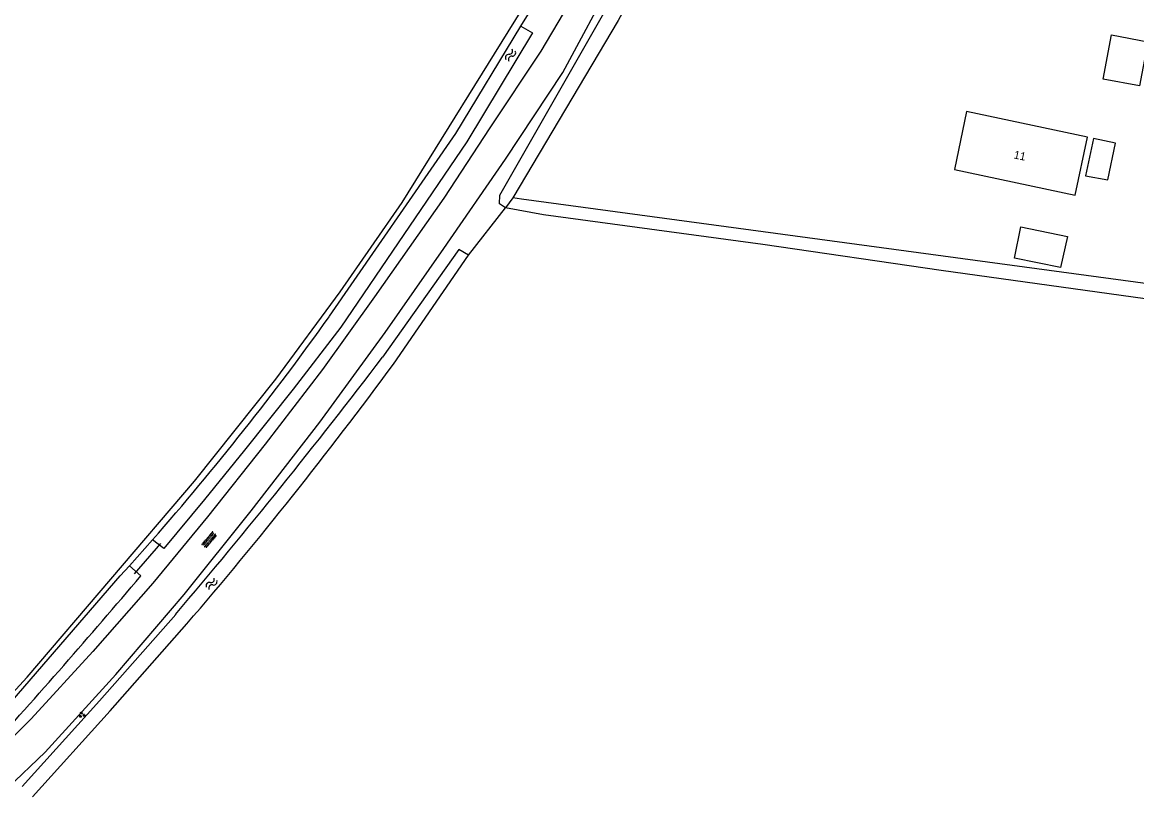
# Model space of a CAD drawing. Extents: x 124000 to 129000, y 395500 to 397503.
# Drawn here: x 125677 to 125816.2, y 397125.3 to 397221.4 of the extents above; entities that cross this region are included whole.
import ezdxf

# ---------------------------------------------------------------- set-up
doc = ezdxf.new("R2010")
doc.units = 0
for name, color, linetype in [('gg-afsc-draadraster', 7, 'Continuous'), ('gg-anno-huisnummerreeks BGT', 7, 'Continuous'), ('gg-bbg-bijgebouw', 7, 'Continuous'), ('gg-bbg-hoofdgebouw', 7, 'Continuous'), ('gg-bbg-luifel en loopbrug', 7, 'Continuous'), ('gg-bbg-open loods', 7, 'Continuous'), ('gg-knt-onverhard', 7, 'Continuous'), ('gg-kntw-bovenkant insteek waterloop', 7, 'Continuous'), ('gg-kwrk-duiker nz buis', 7, 'Continuous'), ('gg-kwrk-stuw', 7, 'Continuous'), ('gt-grn-groengrens', 7, 'Continuous'), ('gt-grn-vlakafsluiter', 7, 'Continuous'), ('gt-symb-groenvak', 7, 'Continuous'), ('gt-symb-overige verharding', 7, 'Continuous'), ('gt-symb-watersymbool', 7, 'Continuous')]:
    doc.layers.add(name, color=color, linetype=linetype)

# ---------------------------------------------------------------- blocks, each defined once
blk = doc.blocks.new('gt0-WA')
at = {"layer": 'gt-symb-watersymbool'}
for centre, start, end in [((-0.32, 0.02), 28.0725, 151.9275), ((0.43, 0.42), 208.0725, 331.9275), ((-0.32, -0.43), 28.0725, 151.9275), ((0.43, -0.03), 208.0725, 331.9275)]:
    blk.add_arc(centre, 0.425, start, end, dxfattribs=at)
blk = doc.blocks.new('gt0-GRVAK')
at = {"layer": 'gt-symb-groenvak'}
for p, q in [((-0.11, 0.19), (-0.23, 0.24)), ((-0.18, 0.15), (0.09, 0.15)), ((-0.09, 0.21), (-0.16, 0.32)), ((-0.05, 0.21), (-0.05, 0.39)), ((0, 0.21), (0.06, 0.32)), ((0.01, 0.19), (0.13, 0.24)), ((0.26, -0.05), (0.2, 0.06)), ((0.3, -0.05), (0.3, 0.13)), ((0.35, -0.05), (0.41, 0.06)), ((-0.25, -0.23), (-0.36, -0.18)), ((-0.32, -0.26), (-0.05, -0.26)), ((-0.23, -0.21), (-0.29, -0.09)), ((-0.18, -0.2), (-0.18, -0.02)), ((-0.14, -0.21), (-0.07, -0.09)), ((-0.12, -0.23), (0, -0.18)), ((0.24, -0.07), (0.12, -0.02)), ((0.17, -0.11), (0.44, -0.11)), ((0.37, -0.07), (0.49, -0.02))]:
    blk.add_line(p, q, dxfattribs=at)
blk = doc.blocks.new('gt0-OVH')
at = {"layer": 'gt-symb-overige verharding'}
for points in [[(-0.97, 0.3), (-0.97, 0.31), (-0.96, 0.32), (-0.97, 0.33), (-0.97, 0.34), (-0.98, 0.35), (-0.99, 0.35), (-1, 0.36), (-1.01, 0.35), (-1.02, 0.35), (-1.03, 0.34), (-1.03, 0.33), (-1.04, 0.32), (-1.03, 0.31), (-1.03, 0.3), (-1.02, 0.29), (-1.01, 0.29), (-1, 0.28), (-0.99, 0.29), (-0.98, 0.29)], [(-0.87, 0.11), (-0.87, 0.12), (-0.86, 0.13), (-0.87, 0.14), (-0.87, 0.15), (-0.88, 0.16), (-0.89, 0.16), (-0.9, 0.16), (-0.91, 0.16), (-0.92, 0.16), (-0.93, 0.15), (-0.93, 0.14), (-0.94, 0.13), (-0.93, 0.12), (-0.93, 0.11), (-0.92, 0.1), (-0.91, 0.09), (-0.9, 0.09), (-0.89, 0.09), (-0.88, 0.1)], [(-0.77, 0.3), (-0.77, 0.31), (-0.76, 0.32), (-0.77, 0.33), (-0.77, 0.34), (-0.78, 0.35), (-0.79, 0.35), (-0.8, 0.36), (-0.81, 0.35), (-0.82, 0.35), (-0.83, 0.34), (-0.83, 0.33), (-0.84, 0.32), (-0.83, 0.31), (-0.83, 0.3), (-0.82, 0.29), (-0.81, 0.29), (-0.8, 0.28), (-0.79, 0.29), (-0.78, 0.29)], [(-0.67, 0.11), (-0.67, 0.12), (-0.66, 0.13), (-0.67, 0.14), (-0.67, 0.15), (-0.68, 0.16), (-0.69, 0.16), (-0.7, 0.16), (-0.71, 0.16), (-0.72, 0.16), (-0.73, 0.15), (-0.73, 0.14), (-0.74, 0.13), (-0.73, 0.12), (-0.73, 0.11), (-0.72, 0.1), (-0.71, 0.09), (-0.7, 0.09), (-0.69, 0.09), (-0.68, 0.1)], [(-0.57, 0.3), (-0.57, 0.31), (-0.56, 0.32), (-0.57, 0.33), (-0.57, 0.34), (-0.58, 0.35), (-0.59, 0.35), (-0.6, 0.36), (-0.61, 0.35), (-0.62, 0.35), (-0.63, 0.34), (-0.63, 0.33), (-0.64, 0.32), (-0.63, 0.31), (-0.63, 0.3), (-0.62, 0.29), (-0.61, 0.29), (-0.6, 0.28), (-0.59, 0.29), (-0.58, 0.29)], [(-0.47, 0.11), (-0.47, 0.12), (-0.46, 0.13), (-0.47, 0.14), (-0.47, 0.15), (-0.48, 0.16), (-0.49, 0.16), (-0.5, 0.16), (-0.51, 0.16), (-0.52, 0.16), (-0.53, 0.15), (-0.53, 0.14), (-0.54, 0.13), (-0.53, 0.12), (-0.53, 0.11), (-0.52, 0.1), (-0.51, 0.09), (-0.5, 0.09), (-0.49, 0.09), (-0.48, 0.1)], [(-0.37, 0.3), (-0.37, 0.31), (-0.36, 0.32), (-0.37, 0.33), (-0.37, 0.34), (-0.38, 0.35), (-0.39, 0.35), (-0.4, 0.36), (-0.41, 0.35), (-0.42, 0.35), (-0.43, 0.34), (-0.43, 0.33), (-0.44, 0.32), (-0.43, 0.31), (-0.43, 0.3), (-0.42, 0.29), (-0.41, 0.29), (-0.4, 0.28), (-0.39, 0.29), (-0.38, 0.29)], [(-0.27, 0.11), (-0.27, 0.12), (-0.26, 0.13), (-0.27, 0.14), (-0.27, 0.15), (-0.28, 0.16), (-0.29, 0.16), (-0.3, 0.16), (-0.31, 0.16), (-0.32, 0.16), (-0.33, 0.15), (-0.33, 0.14), (-0.34, 0.13), (-0.33, 0.12), (-0.33, 0.11), (-0.32, 0.1), (-0.31, 0.09), (-0.3, 0.09), (-0.29, 0.09), (-0.28, 0.1)], [(-0.17, 0.3), (-0.17, 0.31), (-0.16, 0.32), (-0.17, 0.33), (-0.17, 0.34), (-0.18, 0.35), (-0.19, 0.35), (-0.2, 0.36), (-0.21, 0.35), (-0.22, 0.35), (-0.23, 0.34), (-0.23, 0.33), (-0.24, 0.32), (-0.23, 0.31), (-0.23, 0.3), (-0.22, 0.29), (-0.21, 0.29), (-0.2, 0.28), (-0.19, 0.29), (-0.18, 0.29)], [(-0.07, 0.11), (-0.07, 0.12), (-0.06, 0.13), (-0.07, 0.14), (-0.07, 0.15), (-0.08, 0.16), (-0.09, 0.16), (-0.1, 0.16), (-0.11, 0.16), (-0.12, 0.16), (-0.13, 0.15), (-0.13, 0.14), (-0.14, 0.13), (-0.13, 0.12), (-0.13, 0.11), (-0.12, 0.1), (-0.11, 0.09), (-0.1, 0.09), (-0.09, 0.09), (-0.08, 0.1)], [(0.03, 0.3), (0.03, 0.31), (0.04, 0.32), (0.03, 0.33), (0.03, 0.34), (0.02, 0.35), (0.01, 0.35), (0, 0.36), (-0.01, 0.35), (-0.02, 0.35), (-0.03, 0.34), (-0.03, 0.33), (-0.04, 0.32), (-0.03, 0.31), (-0.03, 0.3), (-0.02, 0.29), (-0.01, 0.29), (0, 0.28), (0.01, 0.29), (0.02, 0.29)], [(0.13, 0.11), (0.13, 0.12), (0.14, 0.13), (0.13, 0.14), (0.13, 0.15), (0.12, 0.16), (0.11, 0.16), (0.1, 0.16), (0.09, 0.16), (0.08, 0.16), (0.07, 0.15), (0.07, 0.14), (0.06, 0.13), (0.07, 0.12), (0.07, 0.11), (0.08, 0.1), (0.09, 0.09), (0.1, 0.09), (0.11, 0.09), (0.12, 0.1)], [(0.23, 0.3), (0.23, 0.31), (0.24, 0.32), (0.23, 0.33), (0.23, 0.34), (0.22, 0.35), (0.21, 0.35), (0.2, 0.36), (0.19, 0.35), (0.18, 0.35), (0.17, 0.34), (0.17, 0.33), (0.16, 0.32), (0.17, 0.31), (0.17, 0.3), (0.18, 0.29), (0.19, 0.29), (0.2, 0.28), (0.21, 0.29), (0.22, 0.29)], [(0.33, 0.11), (0.33, 0.12), (0.34, 0.13), (0.33, 0.14), (0.33, 0.15), (0.32, 0.16), (0.31, 0.16), (0.3, 0.16), (0.29, 0.16), (0.28, 0.16), (0.27, 0.15), (0.27, 0.14), (0.26, 0.13), (0.27, 0.12), (0.27, 0.11), (0.28, 0.1), (0.29, 0.09), (0.3, 0.09), (0.31, 0.09), (0.32, 0.1)], [(0.43, 0.3), (0.43, 0.31), (0.44, 0.32), (0.43, 0.33), (0.43, 0.34), (0.42, 0.35), (0.41, 0.35), (0.4, 0.36), (0.39, 0.35), (0.38, 0.35), (0.37, 0.34), (0.37, 0.33), (0.36, 0.32), (0.37, 0.31), (0.37, 0.3), (0.38, 0.29), (0.39, 0.29), (0.4, 0.28), (0.41, 0.29), (0.42, 0.29)], [(0.53, 0.11), (0.53, 0.12), (0.54, 0.13), (0.53, 0.14), (0.53, 0.15), (0.52, 0.16), (0.51, 0.16), (0.5, 0.16), (0.49, 0.16), (0.48, 0.16), (0.47, 0.15), (0.47, 0.14), (0.46, 0.13), (0.47, 0.12), (0.47, 0.11), (0.48, 0.1), (0.49, 0.09), (0.5, 0.09), (0.51, 0.09), (0.52, 0.1)], [(0.63, 0.3), (0.63, 0.31), (0.64, 0.32), (0.63, 0.33), (0.63, 0.34), (0.62, 0.35), (0.61, 0.35), (0.6, 0.36), (0.59, 0.35), (0.58, 0.35), (0.57, 0.34), (0.57, 0.33), (0.56, 0.32), (0.57, 0.31), (0.57, 0.3), (0.58, 0.29), (0.59, 0.29), (0.6, 0.28), (0.61, 0.29), (0.62, 0.29)], [(0.73, 0.11), (0.73, 0.12), (0.74, 0.13), (0.73, 0.14), (0.73, 0.15), (0.72, 0.16), (0.71, 0.16), (0.7, 0.16), (0.69, 0.16), (0.68, 0.16), (0.67, 0.15), (0.67, 0.14), (0.66, 0.13), (0.67, 0.12), (0.67, 0.11), (0.68, 0.1), (0.69, 0.09), (0.7, 0.09), (0.71, 0.09), (0.72, 0.1)], [(0.83, 0.3), (0.83, 0.31), (0.84, 0.32), (0.83, 0.33), (0.83, 0.34), (0.82, 0.35), (0.81, 0.35), (0.8, 0.36), (0.79, 0.35), (0.78, 0.35), (0.77, 0.34), (0.77, 0.33), (0.76, 0.32), (0.77, 0.31), (0.77, 0.3), (0.78, 0.29), (0.79, 0.29), (0.8, 0.28), (0.81, 0.29), (0.82, 0.29)], [(0.93, 0.11), (0.93, 0.12), (0.94, 0.13), (0.93, 0.14), (0.93, 0.15), (0.92, 0.16), (0.91, 0.16), (0.9, 0.16), (0.89, 0.16), (0.88, 0.16), (0.87, 0.15), (0.87, 0.14), (0.86, 0.13), (0.87, 0.12), (0.87, 0.11), (0.88, 0.1), (0.89, 0.09), (0.9, 0.09), (0.91, 0.09), (0.92, 0.1)], [(1.03, 0.3), (1.03, 0.31), (1.04, 0.32), (1.03, 0.33), (1.03, 0.34), (1.02, 0.35), (1.01, 0.35), (1, 0.36), (0.99, 0.35), (0.98, 0.35), (0.97, 0.34), (0.97, 0.33), (0.96, 0.32), (0.97, 0.31), (0.97, 0.3), (0.98, 0.29), (0.99, 0.29), (1, 0.28), (1.01, 0.29), (1.02, 0.29)], [(-0.97, -0.14), (-0.97, -0.13), (-0.96, -0.12), (-0.97, -0.11), (-0.97, -0.1), (-0.98, -0.09), (-0.99, -0.09), (-1, -0.08), (-1.01, -0.09), (-1.02, -0.09), (-1.03, -0.1), (-1.03, -0.11), (-1.04, -0.12), (-1.03, -0.13), (-1.03, -0.14), (-1.02, -0.15), (-1.01, -0.15), (-1, -0.16), (-0.99, -0.15), (-0.98, -0.15)], [(-0.87, -0.33), (-0.87, -0.32), (-0.86, -0.31), (-0.87, -0.3), (-0.87, -0.29), (-0.88, -0.28), (-0.89, -0.28), (-0.9, -0.28), (-0.91, -0.28), (-0.92, -0.28), (-0.93, -0.29), (-0.93, -0.3), (-0.94, -0.31), (-0.93, -0.32), (-0.93, -0.33), (-0.92, -0.34), (-0.91, -0.35), (-0.9, -0.35), (-0.89, -0.35), (-0.88, -0.34)], [(-0.77, -0.14), (-0.77, -0.13), (-0.76, -0.12), (-0.77, -0.11), (-0.77, -0.1), (-0.78, -0.09), (-0.79, -0.09), (-0.8, -0.08), (-0.81, -0.09), (-0.82, -0.09), (-0.83, -0.1), (-0.83, -0.11), (-0.84, -0.12), (-0.83, -0.13), (-0.83, -0.14), (-0.82, -0.15), (-0.81, -0.15), (-0.8, -0.16), (-0.79, -0.15), (-0.78, -0.15)], [(-0.67, -0.33), (-0.67, -0.32), (-0.66, -0.31), (-0.67, -0.3), (-0.67, -0.29), (-0.68, -0.28), (-0.69, -0.28), (-0.7, -0.28), (-0.71, -0.28), (-0.72, -0.28), (-0.73, -0.29), (-0.73, -0.3), (-0.74, -0.31), (-0.73, -0.32), (-0.73, -0.33), (-0.72, -0.34), (-0.71, -0.35), (-0.7, -0.35), (-0.69, -0.35), (-0.68, -0.34)], [(-0.57, -0.14), (-0.57, -0.13), (-0.56, -0.12), (-0.57, -0.11), (-0.57, -0.1), (-0.58, -0.09), (-0.59, -0.09), (-0.6, -0.08), (-0.61, -0.09), (-0.62, -0.09), (-0.63, -0.1), (-0.63, -0.11), (-0.64, -0.12), (-0.63, -0.13), (-0.63, -0.14), (-0.62, -0.15), (-0.61, -0.15), (-0.6, -0.16), (-0.59, -0.15), (-0.58, -0.15)], [(-0.47, -0.33), (-0.47, -0.32), (-0.46, -0.31), (-0.47, -0.3), (-0.47, -0.29), (-0.48, -0.28), (-0.49, -0.28), (-0.5, -0.28), (-0.51, -0.28), (-0.52, -0.28), (-0.53, -0.29), (-0.53, -0.3), (-0.54, -0.31), (-0.53, -0.32), (-0.53, -0.33), (-0.52, -0.34), (-0.51, -0.35), (-0.5, -0.35), (-0.49, -0.35), (-0.48, -0.34)], [(-0.37, -0.14), (-0.37, -0.13), (-0.36, -0.12), (-0.37, -0.11), (-0.37, -0.1), (-0.38, -0.09), (-0.39, -0.09), (-0.4, -0.08), (-0.41, -0.09), (-0.42, -0.09), (-0.43, -0.1), (-0.43, -0.11), (-0.44, -0.12), (-0.43, -0.13), (-0.43, -0.14), (-0.42, -0.15), (-0.41, -0.15), (-0.4, -0.16), (-0.39, -0.15), (-0.38, -0.15)], [(-0.27, -0.33), (-0.27, -0.32), (-0.26, -0.31), (-0.27, -0.3), (-0.27, -0.29), (-0.28, -0.28), (-0.29, -0.28), (-0.3, -0.28), (-0.31, -0.28), (-0.32, -0.28), (-0.33, -0.29), (-0.33, -0.3), (-0.34, -0.31), (-0.33, -0.32), (-0.33, -0.33), (-0.32, -0.34), (-0.31, -0.35), (-0.3, -0.35), (-0.29, -0.35), (-0.28, -0.34)], [(-0.17, -0.14), (-0.17, -0.13), (-0.16, -0.12), (-0.17, -0.11), (-0.17, -0.1), (-0.18, -0.09), (-0.19, -0.09), (-0.2, -0.08), (-0.21, -0.09), (-0.22, -0.09), (-0.23, -0.1), (-0.23, -0.11), (-0.24, -0.12), (-0.23, -0.13), (-0.23, -0.14), (-0.22, -0.15), (-0.21, -0.15), (-0.2, -0.16), (-0.19, -0.15), (-0.18, -0.15)], [(-0.07, -0.33), (-0.07, -0.32), (-0.06, -0.31), (-0.07, -0.3), (-0.07, -0.29), (-0.08, -0.28), (-0.09, -0.28), (-0.1, -0.28), (-0.11, -0.28), (-0.12, -0.28), (-0.13, -0.29), (-0.13, -0.3), (-0.14, -0.31), (-0.13, -0.32), (-0.13, -0.33), (-0.12, -0.34), (-0.11, -0.35), (-0.1, -0.35), (-0.09, -0.35), (-0.08, -0.34)], [(0.03, -0.14), (0.03, -0.13), (0.04, -0.12), (0.03, -0.11), (0.03, -0.1), (0.02, -0.09), (0.01, -0.09), (0, -0.08), (-0.01, -0.09), (-0.02, -0.09), (-0.03, -0.1), (-0.03, -0.11), (-0.04, -0.12), (-0.03, -0.13), (-0.03, -0.14), (-0.02, -0.15), (-0.01, -0.15), (0, -0.16), (0.01, -0.15), (0.02, -0.15)], [(0.13, -0.33), (0.13, -0.32), (0.14, -0.31), (0.13, -0.3), (0.13, -0.29), (0.12, -0.28), (0.11, -0.28), (0.1, -0.28), (0.09, -0.28), (0.08, -0.28), (0.07, -0.29), (0.07, -0.3), (0.06, -0.31), (0.07, -0.32), (0.07, -0.33), (0.08, -0.34), (0.09, -0.35), (0.1, -0.35), (0.11, -0.35), (0.12, -0.34)], [(0.23, -0.14), (0.23, -0.13), (0.24, -0.12), (0.23, -0.11), (0.23, -0.1), (0.22, -0.09), (0.21, -0.09), (0.2, -0.08), (0.19, -0.09), (0.18, -0.09), (0.17, -0.1), (0.17, -0.11), (0.16, -0.12), (0.17, -0.13), (0.17, -0.14), (0.18, -0.15), (0.19, -0.15), (0.2, -0.16), (0.21, -0.15), (0.22, -0.15)], [(0.33, -0.33), (0.33, -0.32), (0.34, -0.31), (0.33, -0.3), (0.33, -0.29), (0.32, -0.28), (0.31, -0.28), (0.3, -0.28), (0.29, -0.28), (0.28, -0.28), (0.27, -0.29), (0.27, -0.3), (0.26, -0.31), (0.27, -0.32), (0.27, -0.33), (0.28, -0.34), (0.29, -0.35), (0.3, -0.35), (0.31, -0.35), (0.32, -0.34)], [(0.43, -0.14), (0.43, -0.13), (0.44, -0.12), (0.43, -0.11), (0.43, -0.1), (0.42, -0.09), (0.41, -0.09), (0.4, -0.08), (0.39, -0.09), (0.38, -0.09), (0.37, -0.1), (0.37, -0.11), (0.36, -0.12), (0.37, -0.13), (0.37, -0.14), (0.38, -0.15), (0.39, -0.15), (0.4, -0.16), (0.41, -0.15), (0.42, -0.15)], [(0.53, -0.33), (0.53, -0.32), (0.54, -0.31), (0.53, -0.3), (0.53, -0.29), (0.52, -0.28), (0.51, -0.28), (0.5, -0.28), (0.49, -0.28), (0.48, -0.28), (0.47, -0.29), (0.47, -0.3), (0.46, -0.31), (0.47, -0.32), (0.47, -0.33), (0.48, -0.34), (0.49, -0.35), (0.5, -0.35), (0.51, -0.35), (0.52, -0.34)], [(0.63, -0.14), (0.63, -0.13), (0.64, -0.12), (0.63, -0.11), (0.63, -0.1), (0.62, -0.09), (0.61, -0.09), (0.6, -0.08), (0.59, -0.09), (0.58, -0.09), (0.57, -0.1), (0.57, -0.11), (0.56, -0.12), (0.57, -0.13), (0.57, -0.14), (0.58, -0.15), (0.59, -0.15), (0.6, -0.16), (0.61, -0.15), (0.62, -0.15)], [(0.73, -0.33), (0.73, -0.32), (0.74, -0.31), (0.73, -0.3), (0.73, -0.29), (0.72, -0.28), (0.71, -0.28), (0.7, -0.28), (0.69, -0.28), (0.68, -0.28), (0.67, -0.29), (0.67, -0.3), (0.66, -0.31), (0.67, -0.32), (0.67, -0.33), (0.68, -0.34), (0.69, -0.35), (0.7, -0.35), (0.71, -0.35), (0.72, -0.34)], [(0.83, -0.14), (0.83, -0.13), (0.84, -0.12), (0.83, -0.11), (0.83, -0.1), (0.82, -0.09), (0.81, -0.09), (0.8, -0.08), (0.79, -0.09), (0.78, -0.09), (0.77, -0.1), (0.77, -0.11), (0.76, -0.12), (0.77, -0.13), (0.77, -0.14), (0.78, -0.15), (0.79, -0.15), (0.8, -0.16), (0.81, -0.15), (0.82, -0.15)], [(0.93, -0.33), (0.93, -0.32), (0.94, -0.31), (0.93, -0.3), (0.93, -0.29), (0.92, -0.28), (0.91, -0.28), (0.9, -0.28), (0.89, -0.28), (0.88, -0.28), (0.87, -0.29), (0.87, -0.3), (0.86, -0.31), (0.87, -0.32), (0.87, -0.33), (0.88, -0.34), (0.89, -0.35), (0.9, -0.35), (0.91, -0.35), (0.92, -0.34)], [(1.03, -0.14), (1.03, -0.13), (1.04, -0.12), (1.03, -0.11), (1.03, -0.1), (1.02, -0.09), (1.01, -0.09), (1, -0.08), (0.99, -0.09), (0.98, -0.09), (0.97, -0.1), (0.97, -0.11), (0.96, -0.12), (0.97, -0.13), (0.97, -0.14), (0.98, -0.15), (0.99, -0.15), (1, -0.16), (1.01, -0.15), (1.02, -0.15)]]:
    blk.add_lwpolyline(points, close=True, dxfattribs=at)

msp = doc.modelspace()

# ---------------------------------------------------------------- linework, layer by layer
at = {"layer": 'gg-afsc-draadraster'}
msp.add_lwpolyline([(125642.65, 397110.93), (125650.08, 397115.76), (125657.43, 397120.69), (125663.34, 397125.22), (125669.13, 397130.47), (125677.55, 397139.59), (125698.48, 397164.07), (125708.62, 397176.8), (125716.67, 397187.69), (125724.43, 397198.85), (125739.37, 397222.94)], dxfattribs=at)
at = {"layer": 'gg-bbg-bijgebouw'}
msp.add_lwpolyline([(125809.84, 397202.2), (125812.6, 397201.69), (125813.57, 397206.29), (125810.81, 397206.87), (125809.84, 397202.2)], dxfattribs=at)
at = {"layer": 'gg-bbg-hoofdgebouw'}
msp.add_line((125794.94, 397210.23), (125793.46, 397202.98), dxfattribs=at)
msp.add_lwpolyline([(125793.46, 397202.98), (125808.54, 397199.8), (125810.06, 397207.04), (125794.94, 397210.23)], dxfattribs=at)
at = {"layer": 'gg-bbg-luifel en loopbrug'}
msp.add_lwpolyline([(125813.08, 397219.8), (125817.61, 397218.95), (125816.57, 397213.44), (125812.04, 397214.29), (125813.08, 397219.8)], dxfattribs=at)
at = {"layer": 'gg-bbg-open loods'}
msp.add_lwpolyline([(125807.6, 397194.64), (125806.7, 397190.74), (125800.95, 397191.92), (125801.75, 397195.84), (125807.6, 397194.64)], dxfattribs=at)
at = {"layer": 'gg-knt-onverhard'}
for points in [[(125756.93, 397250.55), (125751.92, 397237.41), (125747.34, 397227.24), (125741.75, 397217.78), (125735.38, 397208.19), (125729.64, 397199.42), (125720.97, 397187.07), (125714.45, 397178.02), (125707.31, 397168.67), (125700.08, 397159.6), (125693.27, 397151.32), (125685.78, 397142.8), (125678.08, 397134.37), (125669.79, 397126.12), (125660.96, 397118.64), (125651.56, 397112.01), (125641.81, 397105.88), (125631.9, 397099.39), (125622.1, 397093.12), (125612.4, 397086.72), (125602.25, 397080.32), (125592.69, 397074.68)], [(125594.39, 397071.5), (125605.9, 397078.13), (125617.48, 397085.31), (125629.25, 397092.48), (125640.98, 397100.11), (125652.95, 397108.25), (125661.79, 397114.35), (125670.36, 397121.2), (125679.79, 397130.22), (125688.65, 397139.93), (125697.18, 397149.89), (125705.54, 397160.37), (125714.15, 397171.43), (125722.32, 397182.61), (125729.65, 397193.12), (125737.34, 397204.28), (125744.49, 397215.1), (125750.97, 397227.13), (125760.44, 397249.2)]]:
    msp.add_lwpolyline(points, dxfattribs=at)
at = {"layer": 'gg-kntw-bovenkant insteek waterloop'}
for p, q in [((125723.34, 397178.66), (125732.72, 397192.3)), ((125694.62, 397155.63), (125693.23, 397156.73)), ((125690.36, 397153.5), (125691.77, 397152.24))]:
    msp.add_line(p, q, dxfattribs=at)
for points in [[(125737.33, 397198.19), (125736.58, 397198.69), (125736.62, 397199.8), (125749.64, 397222.5), (125760.87, 397242.64), (125762.4, 397241.8)], [(125762.4, 397241.8), (125751.42, 397221.6), (125738.26, 397199.47)], [(125739.27, 397220.88), (125740.7, 397220.05), (125732.5, 397206.46), (125716.76, 397183.28), (125710.81, 397175.55), (125704.74, 397167.92), (125699.71, 397161.75), (125694.62, 397155.63)], [(125715.34, 397184.65), (125731.12, 397207.49), (125739.27, 397220.88)], [(125951.25, 397169.13), (125925.94, 397172.67), (125894.26, 397176.75), (125847.97, 397182.7), (125818.79, 397186.62), (125791.78, 397190.39), (125769.5, 397193.62), (125742.08, 397197.31), (125737.33, 397198.19)], [(125732.72, 397192.3), (125731.52, 397192.99), (125721.98, 397179.55)], [(125671.15, 397131.41), (125689.2, 397152.22), (125690.36, 397153.5)], [(125696.12, 397147.42), (125686.61, 397136.61), (125676.95, 397125.93)], [(125678.22, 397124.61), (125687.94, 397135.36), (125697.52, 397146.24)]]:
    msp.add_lwpolyline(points, dxfattribs=at)
for centre, radius, start, end in [((125430.26, 397387.75), 350.03, 318.7011, 324.5326), ((125104.34, 397650.29), 776.58, 319.64346, 322.68676), ((125278.53, 397506.32), 552.46, 319.3237, 323.6235), ((125031.4, 397711.41), 865.31, 317.78646, 319.74319)]:
    msp.add_arc(centre, radius, start, end, dxfattribs=at)
at = {"layer": 'gg-kwrk-duiker nz buis'}
msp.add_line((125690.97, 397152.48), (125694.28, 397156.29), dxfattribs=at)
at = {"layer": 'gg-kwrk-stuw'}
msp.add_lwpolyline([(125950.31, 397170.7), (125929.42, 397173.33), (125848.76, 397184.52), (125739.33, 397199.3), (125738.26, 397199.47)], dxfattribs=at)
at = {"layer": 'gt-grn-groengrens'}
for p, q in [((125732.72, 397192.3), (125737.33, 397198.19)), ((125693.23, 397156.73), (125690.36, 397153.5))]:
    msp.add_line(p, q, dxfattribs=at)
at = {"layer": 'gt-grn-vlakafsluiter'}
for p, q in [((125739.27, 397220.88), (125740.23, 397222.45)), ((125738.26, 397199.47), (125737.33, 397198.19))]:
    msp.add_line(p, q, dxfattribs=at)

# ---------------------------------------------------------------- block references
at = {"layer": 'gt-symb-groenvak'}
msp.add_blockref('gt0-GRVAK', (125684.4, 397134.87), dxfattribs=at)
at = {"layer": 'gt-symb-overige verharding', "rotation": 49.90831920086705}
msp.add_blockref('gt0-OVH', (125700.32, 397156.73), dxfattribs=at)
at = {"layer": 'gt-symb-watersymbool'}
for p, rotation in [((125737.94, 397217.22), 58.48628372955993), ((125700.56, 397151.21), 48.770950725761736)]:
    msp.add_blockref('gt0-WA', p, dxfattribs=dict(at, rotation=rotation))

# ---------------------------------------------------------------- texts
at = {"layer": 'gg-anno-huisnummerreeks BGT'}
msp.add_text('11', height=1, rotation=348, dxfattribs=at).set_placement((125800.8, 397204.39))

doc.saveas('drawing.dxf')
